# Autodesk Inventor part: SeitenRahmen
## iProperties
Created: 2006-10
Part Number: SeitenRahmen
Document SubType Name: Sheet Metal
Designer: rr
Author: rr
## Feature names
1. Extrusion1
2. Grobblech1
